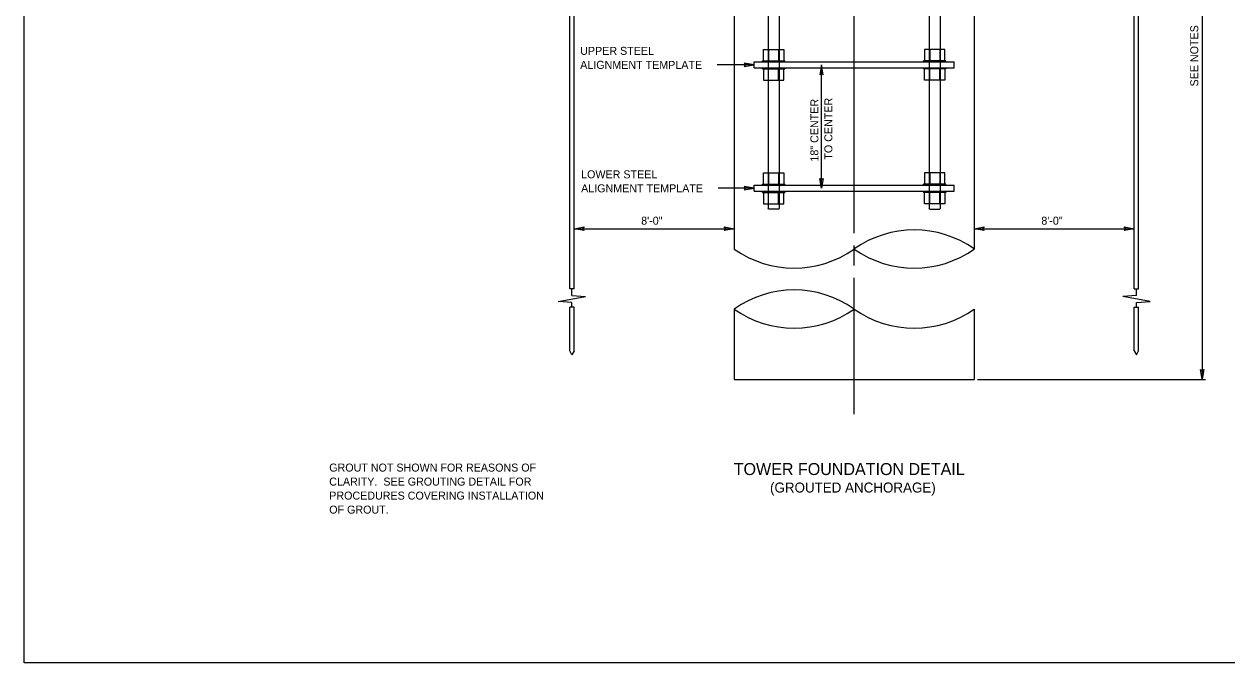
# Model space of a CAD drawing. Extents: x 99978 to 113378, y 99891 to 102182.
# Drawn here: x 105078 to 106882, y 99891 to 100848 of the extents above; entities that cross this region are included whole.
import ezdxf

# ---------------------------------------------------------------- set-up
doc = ezdxf.new("R2010")
doc.units = 0
doc.layers.add('Border Organizer Shape', color=7, linetype='Continuous')
doc.layers.add('Default', color=7, linetype='Continuous')

msp = doc.modelspace()

# ---------------------------------------------------------------- linework, layer by layer
at = {"layer": 'Border Organizer Shape'}
for p, q in [((106193.9, 101344.3), (106193.9, 100579)), ((106210.7, 101344.3), (106210.7, 100579)), ((106435.4, 101344.3), (106435.4, 100579)), ((106452.2, 101344.3), (106452.2, 100579)), ((106845, 101291), (106845, 100315.5)), ((106143.1, 101281.9), (106143.1, 100511)), ((106503.1, 101281.9), (106503.1, 100511)), ((105896.6, 100451.1), (105896.6, 101147)), ((105903.1, 100451.1), (105903.1, 101147)), ((106743, 100451.1), (106743.1, 101147)), ((106749.5, 100451.1), (106749.5, 101124.5)), ((106323.1, 100534.7), (106323.1, 100934.9)), ((106187.2, 100810.1), (106217.4, 100810.1)), ((106187.2, 100793.2), (106187.2, 100810.1)), ((106194.8, 100810.1), (106194.8, 100793.2)), ((106209.8, 100810.1), (106209.8, 100793.2)), ((106217.4, 100810.1), (106217.4, 100793.2)), ((106323.1, 100787.6), (106323.1, 100817.6)), ((106458.9, 100810.1), (106428.7, 100810.1)), ((106428.7, 100810.1), (106428.7, 100793.2)), ((106436.3, 100810.1), (106436.3, 100793.2)), ((106451.3, 100810.1), (106451.3, 100793.2)), ((106458.9, 100793.2), (106458.9, 100810.1)), ((106173.2, 100787.1), (106117.5, 100787.1)), ((106173.2, 100791.6), (106473, 100791.6)), ((106173.2, 100782.6), (106173.2, 100791.6)), ((106185.4, 100793.2), (106219.2, 100793.2)), ((106185.4, 100791.6), (106185.4, 100793.2)), ((106219.2, 100791.6), (106219.2, 100793.2)), ((106274, 100602), (106274, 100787.1)), ((106460.7, 100793.2), (106426.9, 100793.2)), ((106426.9, 100791.6), (106426.9, 100793.2)), ((106460.7, 100791.6), (106460.7, 100793.2)), ((106472.9, 100782.6), (106472.9, 100791.6)), ((106173.2, 100782.6), (106473, 100782.6)), ((106185.4, 100780.9), (106185.4, 100782.6)), ((106185.4, 100780.9), (106219.2, 100780.9)), ((106187.2, 100780.9), (106187.2, 100764)), ((106194.8, 100764), (106194.8, 100780.9)), ((106209.8, 100764), (106209.8, 100780.9)), ((106217.4, 100764), (106217.4, 100780.9)), ((106219.2, 100782.6), (106219.2, 100780.9)), ((106426.9, 100782.6), (106426.9, 100780.9)), ((106460.7, 100780.9), (106426.9, 100780.9)), ((106428.7, 100764), (106428.7, 100780.9)), ((106436.3, 100764), (106436.3, 100780.9)), ((106451.3, 100764), (106451.3, 100780.9)), ((106458.9, 100780.9), (106458.9, 100764)), ((106460.7, 100782.6), (106460.7, 100780.9)), ((106187.2, 100764), (106217.4, 100764)), ((106458.9, 100764), (106428.7, 100764)), ((106187.2, 100625.1), (106217.4, 100625.1)), ((106187.2, 100608.2), (106187.2, 100625.1)), ((106194.8, 100625.1), (106194.8, 100608.2)), ((106209.8, 100625.1), (106209.8, 100608.2)), ((106217.4, 100625.1), (106217.4, 100608.2)), ((106323, 100602.6), (106323, 100632.6)), ((106458.9, 100625.1), (106428.7, 100625.1)), ((106428.7, 100625.1), (106428.7, 100608.2)), ((106436.3, 100625.1), (106436.3, 100608.2)), ((106451.3, 100625.1), (106451.3, 100608.2)), ((106458.9, 100608.2), (106458.9, 100625.1)), ((106173.2, 100606.5), (106472.9, 100606.5)), ((106173.2, 100597.5), (106173.2, 100606.5)), ((106185.4, 100608.2), (106219.2, 100608.2)), ((106185.4, 100606.5), (106185.4, 100608.2)), ((106219.2, 100606.5), (106219.2, 100608.2)), ((106460.7, 100608.2), (106426.9, 100608.2)), ((106426.9, 100606.5), (106426.9, 100608.2)), ((106460.7, 100606.5), (106460.7, 100608.2)), ((106472.9, 100597.5), (106472.9, 100606.5)), ((106173.2, 100602), (106119, 100602)), ((106173.2, 100597.5), (106472.9, 100597.5)), ((106185.4, 100595.9), (106185.4, 100597.5)), ((106185.4, 100595.9), (106219.2, 100595.9)), ((106187.2, 100595.9), (106187.2, 100579)), ((106194.8, 100579), (106194.8, 100595.9)), ((106209.8, 100579), (106209.8, 100595.9)), ((106217.4, 100579), (106217.4, 100595.9)), ((106219.2, 100597.5), (106219.2, 100595.9)), ((106426.9, 100597.5), (106426.9, 100595.9)), ((106460.7, 100595.9), (106426.9, 100595.9)), ((106428.7, 100579), (106428.7, 100595.9)), ((106436.3, 100579), (106436.3, 100595.9)), ((106451.3, 100579), (106451.3, 100595.9)), ((106458.9, 100595.9), (106458.9, 100579)), ((106460.7, 100597.5), (106460.7, 100595.9)), ((106187.2, 100579), (106217.4, 100579)), ((106193.9, 100579), (106193.9, 100571.6)), ((106194.7, 100570.8), (106193.9, 100571.6)), ((106209.9, 100570.8), (106194.7, 100570.8)), ((106209.9, 100570.8), (106210.7, 100571.6)), ((106210.7, 100579), (106210.7, 100571.6)), ((106458.9, 100579), (106428.7, 100579)), ((106435.4, 100579), (106435.4, 100571.6)), ((106436.2, 100570.8), (106435.4, 100571.6)), ((106436.2, 100570.8), (106451.4, 100570.8)), ((106451.4, 100570.8), (106452.2, 100571.6)), ((106452.2, 100579), (106452.2, 100571.6)), ((105903.1, 100541.5), (106143.1, 100541.5)), ((106503, 100541.5), (106743, 100541.5)), ((106323.1, 100486.2), (106323.1, 100516.2)), ((106323.1, 100263.3), (106323.1, 100467.9)), ((105903.1, 100451.1), (105896.6, 100451.1)), ((105899.7, 100441.3), (105899.7, 100451.1)), ((105899.7, 100441.3), (105920, 100439.7)), ((106746.4, 100441.3), (106726.1, 100439.7)), ((106743, 100451.1), (106749.5, 100451.1)), ((106746.4, 100441.3), (106746.4, 100451.1)), ((105879.4, 100432.5), (105920, 100439.7)), ((105899.7, 100430.8), (105879.4, 100432.5)), ((105896.6, 100358.6), (105896.6, 100424.1)), ((105903.1, 100424.1), (105896.6, 100424.1)), ((105899.7, 100424.1), (105899.7, 100430.8)), ((105903.1, 100358.6), (105903.1, 100424.1)), ((106766.7, 100432.5), (106726.1, 100439.7)), ((106743, 100358.6), (106743, 100424.1)), ((106743, 100424.1), (106749.5, 100424.1)), ((106746.4, 100430.8), (106766.7, 100432.5)), ((106746.4, 100424.1), (106746.4, 100430.8)), ((106749.5, 100358.6), (106749.5, 100424.1)), ((106143.1, 100421), (106143.1, 100315.5)), ((106503.1, 100421), (106503, 100315.5)), ((105899.8, 100352.6), (105896.6, 100358.6)), ((105903.1, 100358.6), (105899.8, 100352.6)), ((106743, 100358.6), (106746.3, 100352.6)), ((106746.3, 100352.6), (106749.5, 100358.6)), ((106143.1, 100315.5), (106503, 100315.5)), ((106508, 100315.5), (106850, 100315.5))]:
    msp.add_line(p, q, dxfattribs=at)
for points in [[(106158.3, 100784.5), (106173.2, 100787.1), (106158.3, 100789.6), (106160.6, 100787.1)], [(106276.5, 100772.2), (106274, 100787.1), (106271.4, 100772.2), (106274, 100774.5)], [(106158.2, 100599.5), (106173.2, 100602), (106158.2, 100604.6), (106160.6, 100602)], [(106276.5, 100616.9), (106274, 100602), (106271.4, 100616.9), (106274, 100614.6)], [(105918, 100539), (105903.1, 100541.5), (105918, 100544.1), (105915.6, 100541.5)], [(106128.1, 100544.1), (106143.1, 100541.5), (106128.1, 100539), (106130.5, 100541.5)], [(106518, 100539), (106503, 100541.5), (106518, 100544.1), (106515.6, 100541.5)], [(106728.1, 100544.1), (106743, 100541.5), (106728.1, 100539), (106730.5, 100541.5)], [(106847.5, 100330.4), (106845, 100315.5), (106842.5, 100330.4), (106845, 100328)]]:
    msp.add_lwpolyline(points, close=True, dxfattribs=at)
for centre, start, end in [((106413.1, 100384), 54.6933, 125.3067), ((106233.1, 100638.1), 234.6933, 305.3067), ((106413.1, 100638.1), 234.6933, 305.3067), ((106233.1, 100294), 54.6933, 125.3067), ((106233.1, 100548.1), 234.6933, 305.3067), ((106413.1, 100548.1), 234.6933, 305.3067)]:
    msp.add_arc(centre, 155.7, start, end, dxfattribs=at)
at = {"layer": 'Default'}
msp.add_lwpolyline([(105078.4, 102090.2), (108278.1, 102090.2), (108278.1, 99890.6), (105078.4, 99890.6)], close=True, dxfattribs=at)

# ---------------------------------------------------------------- texts
at = {"layer": 'Border Organizer Shape'}
for s, p in [('SEE NOTES', (106839, 100754.7)), ('18" CENTER', (106269.4, 100642.1)), ('TO CENTER', (106290.4, 100645))]:
    msp.add_text(s, height=12, rotation=90, dxfattribs=at).set_placement(p)
for s, height, p in [('UPPER STEEL ', 12, (105912.3, 100802.1)), ('ALIGNMENT TEMPLATE ', 12, (105912.3, 100781.1)), ('LOWER STEEL ', 12, (105913.7, 100617)), ('ALIGNMENT TEMPLATE ', 12, (105913.7, 100596)), ('8\'-0"', 12, (106003.7, 100547.5)), ('8\'-0"', 12, (106603.7, 100547.5)), ('GROUT NOT SHOWN FOR REASONS OF ', 12, (105536, 100177.4)), ('TOWER FOUNDATION DETAIL', 18, (106142.5, 100172.2)), ('CLARITY.  SEE GROUTING DETAIL FOR ', 12, (105536, 100156.4)), ('(GROUTED ANCHORAGE)', 15, (106196.9, 100146)), ('PROCEDURES COVERING INSTALLATION ', 12, (105536, 100135.4)), ('OF GROUT.', 12, (105536, 100114.4))]:
    msp.add_text(s, height=height, dxfattribs=at).set_placement(p)

doc.saveas('drawing.dxf')
